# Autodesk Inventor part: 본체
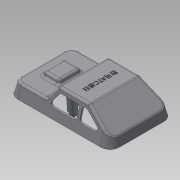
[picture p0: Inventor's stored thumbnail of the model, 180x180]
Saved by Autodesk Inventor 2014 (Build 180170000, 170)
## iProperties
Created: 2015-05
Part Number: 본체
Material: Generic
Document SubType Name: Modeling
Designer: Administrator
Density: 1 g/cm^3
Appearance: Default
Mass: 31.5208 g
Surface Area: 315.397 cm^2
Volume: 31.5208 cm^3
Author: Administrator
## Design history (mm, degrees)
sketch "스케치1"
  geometry: L1 (-49, -38)-(49, -38); L2 (61, -26)-(61, 26); L3 (49, 38)-(-49, 38); L4 (-61, 26)-(-61, -26); L5 (-61, -38)-(61, 38); L6 (61, -38)-(-61, 38); A1 r 12 centre (-49, 26) between (-49, 38) and (-61, 26); A2 r 12 centre (-49, -26) between (-61, -26) and (-49, -38); A3 r 12 centre (49, -26) between (49, -38) and (61, -26); A4 r 12 centre (49, 26) between (61, 26) and (49, 38); 1 further point
  constraints: 12 end point, 8 point on circle, 8 point on line, 8 tangent, 4 centre point, 3 equal radius, 2 midpoint, 2 parallel, 1 horizontal, 1 perpendicular
  dimensions: "d0" = 122 distance of L5.end L6.end; "d1" = 76 distance of L6.start L5.end; "d2" = 12 radius of A1
extrude "돌출1" new body sketch "스케치1" distance "d3" = 30; taper "d4" = -15 deg
sketch "스케치2"
  geometry: L1 (-28.321, 30)-(-58.321, 30); L2 (-58.321, 30)-(-58.321, 10); L3 (-58.321, 10)-(-28.321, 30); L4 (49, 30)-(-49, 30) reference; L5 (-61, 0)-(-52.962, 30) reference; L6 (49, 0)-(-49, 0) reference; 1 further point
  constraints: 6 end point, 1 horizontal, 1 perpendicular, 1 point on line
  dimensions: "d6" = 30 distance of L1.start L1.end; "d11" = 30 distance between parallel lines of L6 L1; "d12" = 20 distance of L1.end L2.end
extrude "돌출2" cut sketch "스케치2" stored distance "d13" = 30; taper "d14" = 0 deg
sketch "스케치3"
  geometry: L1 (49, 0)-(-49, 0) reference; L2 (49, 0)-(61, 0) reference; L3 (49, 30)-(-28.321, 30) reference; L4 (19, 14.382)-(34.522, 14.382); L5 (34.522, 14.382)-(61, 14.382); L6 (61, 0)-(52.962, 30) reference; L7 (19, 14.382)-(8.064, 30); L8 (8.064, 30)-(52.962, 30); L9 (57.146, 14.382)-(52.962, 30); 1 further point
  constraints: 10 end point, 3 point on line, 2 collinear, 2 parallel
  dimensions: "d17" = 42 horizontal distance of L4.start L2.end; "d20" = 125 deg angle of L7 L4
extrude "돌출3" cut sketch "스케치3" stored distance "d21" = 30; taper "d22" = 0 deg
sketch "스케치4"
  geometry: L1 (4.527, 47.146)-(24.527, 47.146); L2 (24.527, 47.146)-(24.527, 21.146); L3 (24.527, 21.146)-(4.527, 21.146); L4 (4.527, 21.146)-(4.527, 47.146); L5 (-12, 8.146)-(-12, 60.146) reference; L6 (98, -3.854)-(0, -3.854) reference; 3 further points
  constraints: 8 end point, 2 midpoint, 2 parallel, 1 horizontal, 1 horizontal alignment, 1 perpendicular
  dimensions: "d23" = 20 distance of L1.start L1.end; "d26" = 26 distance of L1.end L2.end; "d27" = 38 distance from line of L6 point (4.527, 34.146) (derived)
extrude "돌출4" join sketch "스케치4" distance "d28" = 5; taper "d29" = 0 deg
fillet "모깎기1" dims "d30" = 3
fillet "모깎기2" dims "d31" = 3
fillet "모깎기3" dims "d32" = 3
feature "쉘2" dims "d34" = 2
sketch "스케치5"
  geometry: L1 (6.502, 30)-(-27.412, 30) reference; L2 (-29.076, 29.496)-(-50.664, 15.104) reference; L3 (18.104, 15.661)-(8.96, 28.721) reference; L4 (12.659, 14.721)-(6.357, 23.721); L5 (3.899, 25)-(-15.036, 25); L6 (10.201, 10)-(-15.036, 10); L7 (-18.036, 13)-(-18.036, 22); A1 r 3 centre (10.201, 13) between (10.201, 10) and (12.659, 14.721); A2 r 3 centre (3.899, 22) between (6.357, 23.721) and (3.899, 25); A3 r 3 centre (-15.036, 22) between (-15.036, 25) and (-18.036, 22); A4 r 3 centre (-15.036, 13) between (-18.036, 13) and (-15.036, 10); 4 further points
  constraints: 8 end point, 8 point on circle, 8 tangent, 6 point on line, 4 centre point, 3 equal radius, 3 parallel, 1 perpendicular
  dimensions: "d35" = 5 distance between parallel lines of L4 L3; "d36" = 5 distance between parallel lines of L1 L5; "d37" = 34 distance of point (15.964, 10) point (-18.036, 10); "d38" = 15 distance of point (-18.036, 10) point (-18.036, 25); "d39" = 3 radius of A1
extrude "돌출5" cut sketch "스케치5" stored distance "d40" = 5; taper "d41" = 0 deg
sketch "스케치6"
  geometry: L1 (-50.664, 15.104)-(-29.076, 29.496) reference; L2 (-27.412, 30)-(6.502, 30) reference; L3 (49, 0)-(-49, 0) reference; L4 (-41.062, 15.496)-(-27.562, 24.496); L5 (-25.898, 25)-(-24.307, 25); L6 (-39.398, 10)-(-24.307, 10); L7 (-21.307, 13)-(-21.307, 22); A1 r 3 centre (-25.898, 22) between (-25.898, 25) and (-27.562, 24.496); A2 r 3 centre (-24.307, 22) between (-21.307, 22) and (-24.307, 25); A3 r 3 centre (-24.307, 13) between (-24.307, 10) and (-21.307, 13); A4 r 3 centre (-39.398, 13) between (-41.062, 15.496) and (-39.398, 10); 3 further points
  constraints: 8 end point, 8 point on circle, 8 tangent, 4 centre point, 4 point on line, 3 equal radius, 3 parallel, 1 perpendicular
  dimensions: "d42" = 5 distance between parallel lines of L1 L4; "d43" = 5 distance between parallel lines of L2 L5; "d45" = 28 distance of point (-49.307, 10) point (-21.307, 10); "d46" = 15 distance between parallel lines of L5 L6; "d47" = 3 radius of A1
extrude "돌출6" cut sketch "스케치6" stored distance "d48" = 5; taper "d49" = 0 deg
sketch "스케치7"
  geometry: L1 (58.929, 26)-(58.929, -26) reference; L2 (49, -35.929)-(-49, -35.929) reference; L3 (-58.929, -26)-(-58.929, 26) reference; L4 (-49, 35.929)-(49, 35.929) reference; L5 (59.929, 26)-(59.929, -26); L6 (49, -36.929)-(-49, -36.929); L7 (-59.929, -26)-(-59.929, 26); L8 (-49, 36.929)-(49, 36.929); A1 r 9.929 centre (49, 26) between (58.929, 26) and (49, 35.929) reference; A2 r 9.929 centre (49, -26) between (49, -35.929) and (58.929, -26) reference; A3 r 9.929 centre (-49, -26) between (-58.929, -26) and (-49, -35.929) reference; A4 r 9.929 centre (-49, 26) between (-49, 35.929) and (-58.929, 26) reference; A5 r 10.929 centre (49, 26) between (59.929, 26) and (49, 36.929); A6 r 10.929 centre (49, -26) between (49, -36.929) and (59.929, -26); A7 r 10.929 centre (-49, -26) between (-59.929, -26) and (-49, -36.929); A8 r 10.929 centre (-49, 26) between (-49, 36.929) and (-59.929, 26); 1 further point
  constraints: 8 end point, 8 point on circle, 4 centre point, 7 other
  dimensions: "d50" = 1 distance between parallel lines of L4 L8
extrude "돌출7" join sketch "스케치7" distance "d51" = 1; taper "d52" = 0 deg
node "작업 평면1"
sketch "스케치8"
  geometry: A1 r 4 centre (21, 0) between (25, 0) and (17, 0); A2 r 4 centre (10, 0) between (14, 0) and (6, 0); A3 r 4 centre (-10, 0) between (-6, 0) and (-14, 0); A4 r 4 centre (-21, 0) between (-17, 0) and (-25, 0); 3 further points
  constraints: 8 point on circle, 4 centre point, 2 horizontal alignment, 9 other
  dimensions: "d54" = 8 diameter of A4; "d55" = 8 diameter of A3; "d56" = 8 diameter of A2; "d57" = 8 diameter of A1; "d58" = 10 distance of A3.centre point (0, 0); "d59" = 20 distance of A3.centre A2.centre; "d60" = 11 distance of A2.centre A1.centre; "d61" = 11 distance of A4.centre A3.centre
extrude "돌출8" join sketch "스케치8" stored distance "d62" = 8 (= d57); taper "d63" = 0 deg
chamfer "모따기1" distance "d64" = 1; stored, may be unused: second distance "d65" = 2, angle "d66" = 45 deg
sketch "스케치9"
  geometry: L1 (-61, 26)-(-61, -26) reference; C1 r 3 at (-40, 0); 2 further points
  constraints: 1 centre point, 1 horizontal alignment, 1 midpoint
  dimensions: "d68" = 6 diameter of C1; "d69" = 21 distance from line of C1.centre L1
extrude "돌출9" join sketch "스케치9" stored distance "d71" = 8 (= d57); taper "d72" = 2.5 deg
sketch "스케치10"
  geometry: L1 (-26.487, 10)-(-26.487, -10) reference; L2 (-41.473, 10.986)-(-27.473, 10.986) reference; L3 (-42.459, -10)-(-42.459, 10) reference; L4 (-27.473, -10.986)-(-41.473, -10.986) reference; C1 r 3 at (-34.473, 0); 3 further points
  constraints: 2 midpoint, 1 centre point, 1 horizontal alignment, 1 vertical alignment
  dimensions: "d73" = 6 diameter of C1
extrude "돌출10" join sketch "스케치10" stored distance "d74" = 8 (= d57); taper "d75" = 2.5 deg
node "작업 평면2"
sketch "스케치13"
  geometry: C1 r 3 at (0, 22); C2 r 3 at (34.473, 0) reference; C3 r 3 at (-40, 0) reference; 1 further point
  constraints: 1 centre point
  dimensions: "d89" = 6 diameter of C1; "d91" = 22 vertical distance of C1.centre C3.centre; "d92" = 40 horizontal distance of C1.centre C3.centre
extrude "돌출13" join sketch "스케치13" stored distance "d93" = 8 (= d57); taper "d94" = 2.5 deg
node "작업 평면3"
sketch "스케치15"
  geometry: L1 (45, 1)-(35, 1); L2 (35, 1)-(35, -1); L3 (35, -1)-(45, -1); L4 (45, -1)-(45, 1); L5 (45, 1)-(35, -1); L6 (35, 1)-(45, -1); L7 (5, -21)-(-5, -21); L8 (-5, -21)-(-5, -23); L9 (-5, -23)-(5, -23); L10 (5, -23)-(5, -21); L11 (5, -21)-(-5, -23); L12 (-5, -21)-(5, -23); L13 (5, 23)-(-5, 23); L14 (-5, 23)-(-5, 21); L15 (-5, 21)-(5, 21); L16 (5, 21)-(5, 23); L17 (5, 23)-(-5, 21); L18 (-5, 23)-(5, 21); L19 (-29.473, 1)-(-39.473, 1); L20 (-39.473, 1)-(-39.473, -1); L21 (-39.473, -1)-(-29.473, -1); L22 (-29.473, -1)-(-29.473, 1); L23 (-29.473, 1)-(-39.473, -1); L24 (-39.473, 1)-(-29.473, -1); C1 r 3 at (40, 0) reference; C2 r 3 at (0, 22) reference; C3 r 3 at (0, -22) reference; C4 r 3 at (-34.473, 0) reference; 1 further point
  constraints: 48 end point, 8 midpoint, 8 parallel, 4 horizontal, 4 perpendicular
  dimensions: "d96" = 10 distance of L1.start L1.end; "d97" = 2 distance of L1.end L2.end; "d98" = 10 distance of L14.end L15.end; "d99" = 2 distance of L13.end L14.end; "d100" = 10 distance of L7.start L7.end; "d101" = 2 distance of L7.end L8.end; "d102" = 10 distance of L19.start L19.end; "d103" = 2 distance of L19.end L20.end
extrude "돌출14" join sketch "스케치15" stored distance "d104" = 8 (= d57); taper "d105" = 2 deg
sketch "스케치16"
  geometry: L1 (2.079, 0)-(2.616, -15.391) reference; L2 (-2.921, 0.035)-(-2.921, -15.337); L3 (-7.921, 0.07)-(-8.458, -15.284) reference; L4 (-7.921, 0.07)-(-10.647, -15.391); L5 (2.079, 0)-(4.793, -15.391); L6 (4.079, -14.121)-(-9.921, -14.121) reference; L7 (4.079, -16.987)-(-9.921, -16.987) reference; L8 (2.079, 0)-(2.572, -14.121); L9 (-7.921, 0.07)-(-8.417, -14.121); L10 (2.572, -14.121)-(2.616, -15.391); L11 (2.616, -15.391)-(4.793, -15.391); L12 (-8.417, -14.121)-(-8.462, -15.391); L13 (-8.462, -15.391)-(-10.647, -15.391); L14 (76.552, 0.07)-(77.046, -14.052) reference; L15 (66.552, 0.07)-(65.796, -21.538) reference; L16 (82.216, -11.962)-(60.628, -26.479) reference; L17 (71.552, 0.035)-(71.552, -19.133); L18 (76.552, 0.07)-(79.049, -14.091); L19 (71.552, -19.133)-(63.166, -19.133); L20 (71.552, -19.133)-(79.049, -14.091); L21 (66.552, 0.07)-(63.166, -19.133); L22 (65.88, -19.133)-(66.552, 0.07); L23 (76.552, 0.07)-(77.046, -14.052); L24 (77.046, -14.052)-(77.05, -14.161); L25 (77.048, -14.106)-(78.839, -12.902); 30 further points; 13 other entities
  constraints: 36 end point, 9 point on line, 6 collinear, 2 vertical, 1 midpoint, 1 parallel, 1 perpendicular, 21 other
  dimensions: "d106" = 10 deg angle of L5 L2; "d107" = 20 deg angle of L4 L5; "d110" = 10 deg angle of L18 L17; "d112" = 20 deg angle of L18 L21
  node "투영된 루프7"
  node "투영된 루프8"
extrude "돌출15" join sketch "스케치16" stored distance "d108" = 8 (= d57); taper "d109" = 0 deg
extrude "돌출16" join sketch "스케치16" stored distance "d113" = 8 (= d57); taper "d114" = 0 deg
sketch "스케치19"
  geometry: L1 (-26.016, -0.908)-(-26.016, 2.908) reference; L2 (0, 0)-(-26.016, -0.908) reference; L3 (0, 0)-(0, 2) reference; L4 (0, 2)-(-26.016, 2.908) reference; L5 (-25.603, 2.908)-(-25.603, -0.908) reference; L6 (0.349, 2)-(-25.603, 2.908) reference; L7 (0.349, 2)-(0.349, 0) reference; L8 (0.349, 0)-(-25.603, -0.908) reference; L9 (-25.81, 1)-(0.174, 1); L10 (0.349, 2)-(-26.217, 6.684); L11 (0.349, 0)-(-26.168, -4.676); L12 (-26.217, 50.66)-(-26.217, -4.66) reference; L13 (0.349, 0)-(-26.217, -0.929); L14 (0.349, 2)-(-26.217, 2.929); L15 (-26.217, 2.929)-(-26.217, 6.684); L16 (-25.583, -4.66)-(-25.583, 50.66) reference; L17 (-25.583, 6.572)-(-25.603, 2.908); L18 (-25.603, -0.908)-(-25.583, -4.572); 12 further points; 5 other entities
  constraints: 16 end point, 7 point on line, 3 collinear, 1 perpendicular, 9 other
  dimensions: "d119" = 10 deg angle of L10 L9; "d120" = 10 deg angle of L11 L9
  node "투영된 루프12"
  node "투영된 루프13"
sketch "스케치20"
  geometry: L1 (61, 26)-(61, -26) reference; 2 further points
  constraints: 1 horizontal alignment, 1 other
  dimensions: "d121" = 50 distance from line of point (11, 0) L1
feature "엠보싱1" sketch "스케치20" dims "d0" = 122, "d1" = 76, "d2" = 12, "d122" = 0.5, "d123" = 0
sketch "스케치21"
  geometry: C1 r 3 at (0, 0) reference; C2 r 3 at (-34.473, 22) reference; C3 r 3 at (-74.473, 0) reference; C4 r 3 at (-34.473, -22) reference; 5 further points
  constraints: 4 coincident
hole "구멍1" sketch "스케치21" at (0, 0), (-34.473, -22), (-34.473, 22), (-74.473, 0) diameter "d124" = 3.242; stored, may be unused: countersink angle "d128" = 90 deg, drill point angle "d130" = 118 deg; dims "d125" = 9, "d126" = 4, "d127" = 2, "d129" = 11
node "솔리드1"
mirror "대칭1"
node "투영된 루프3"
node "투영된 루프4"
node "투영된 루프5"
node "투영된 루프6"
node "투영된 루프14"
node "투영된 루프15"
other parameters: "d53" = -63, "d82" = 2, "d95" = 2, "d111" = 20 deg
